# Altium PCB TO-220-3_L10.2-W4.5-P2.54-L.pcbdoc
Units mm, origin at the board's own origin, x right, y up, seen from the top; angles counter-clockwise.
Board outline 23.21 x 17.92 mm, 2 copper layers (Top Layer, Bottom Layer), stack 0 mm thick; 1 components, 0 nets, 3 pads, 0 vias.
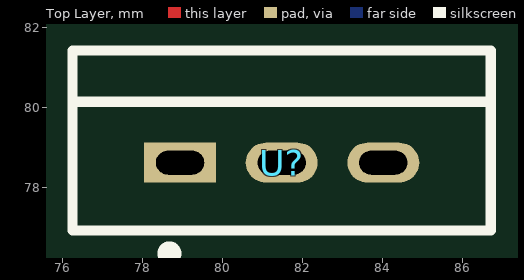
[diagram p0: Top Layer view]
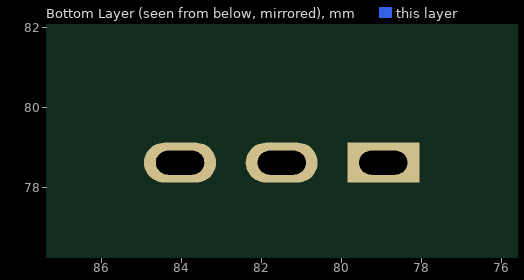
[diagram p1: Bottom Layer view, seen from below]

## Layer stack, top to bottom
Top Layer: signal copper (thickness not stored)
Bottom Layer: signal copper (thickness not stored)

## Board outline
93.064,69.85 69.85,69.85 69.85,87.769 93.064,87.769

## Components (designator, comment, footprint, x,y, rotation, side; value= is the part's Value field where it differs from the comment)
U? "" TO-220-3_L10.2-W4.5-P2.54-L 81.487,78.619 r0 top

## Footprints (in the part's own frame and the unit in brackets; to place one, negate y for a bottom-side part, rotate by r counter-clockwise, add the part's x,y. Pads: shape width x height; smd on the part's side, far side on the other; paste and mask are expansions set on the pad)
TO-220-3_L10.2-W4.5-P2.54-L [mm]
  rect 1.8x1 hole 0.6 slot 1.2 at 0 deg: 1(-2.54,0)
  oval 1.8x1 hole 0.6 slot 1.2 at 0 deg: 2(0,0) 3(2.54,0)
  silkscreen extent -5.23,-2.42 5.23,2.8

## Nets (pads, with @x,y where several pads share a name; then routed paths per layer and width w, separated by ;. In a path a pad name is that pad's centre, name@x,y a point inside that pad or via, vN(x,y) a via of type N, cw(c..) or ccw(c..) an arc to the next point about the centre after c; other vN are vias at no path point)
pads on no net: U?.1 U?.2 U?.3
